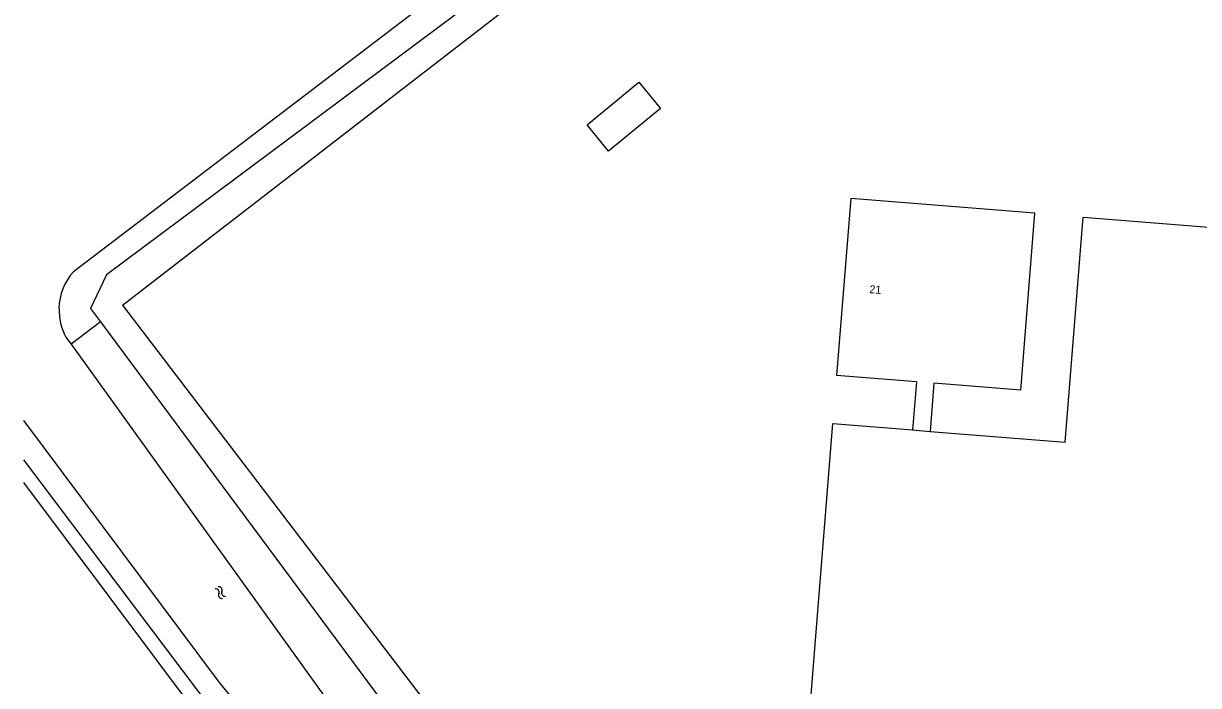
# Model space of a CAD drawing. Extents: x 131000 to 133013, y 393000 to 396501.
# Drawn here: x 131000 to 131146.8, y 394452.9 to 394535.6 of the extents above; entities that cross this region are included whole.
import ezdxf

# ---------------------------------------------------------------- set-up
doc = ezdxf.new("R2010")
doc.units = 0
for name, color, linetype in [('gg-afsc-hekwerk', 7, 'Continuous'), ('gg-anno-huisnummerreeks BGT', 7, 'Continuous'), ('gg-bbg-bijgebouw', 7, 'Continuous'), ('gg-bbg-gedigitaliseerde bebouwing', 7, 'Continuous'), ('gg-bbg-gedigitaliseerde bijgebouw', 7, 'Continuous'), ('gg-bbg-hoofdgebouw', 7, 'Continuous'), ('gg-bbg-tussenscheiding', 7, 'Continuous'), ('gg-kntw-bovenkant insteek waterloop', 7, 'Continuous'), ('gg-kntw-waterlijn', 7, 'Continuous'), ('gt-grn-groengrens', 7, 'Continuous'), ('gt-symb-watersymbool', 7, 'Continuous')]:
    doc.layers.add(name, color=color, linetype=linetype)

# ---------------------------------------------------------------- blocks, each defined once
blk = doc.blocks.new('gt0-WA')
at = {"layer": 'gt-symb-watersymbool'}
for centre, start, end in [((-0.32, 0.02), 28.0725, 151.9275), ((0.43, 0.42), 208.0725, 331.9275), ((-0.32, -0.43), 28.0725, 151.9275), ((0.43, -0.03), 208.0725, 331.9275)]:
    blk.add_arc(centre, 0.425, start, end, dxfattribs=at)

msp = doc.modelspace()

# ---------------------------------------------------------------- linework, layer by layer
at = {"layer": 'gg-afsc-hekwerk'}
for p, q in [((131012.35, 394500.41), (131059.53, 394438.61)), ((131000, 394478.25), (131040.62, 394424))]:
    msp.add_line(p, q, dxfattribs=at)
msp.add_lwpolyline([(131012.35, 394500.41), (131062.93, 394539.51), (131090.58, 394539.97), (131100.72, 394540.82)], dxfattribs=at)
at = {"layer": 'gg-bbg-bijgebouw'}
for points in [[(131130.13, 394483.29), (131132.37, 394511.42), (131203.44, 394505.74), (131196.29, 394415.81)], [(131116.16, 394422), (131096.16, 394423.6), (131101.1, 394485.6)]]:
    msp.add_lwpolyline(points, dxfattribs=at)
at = {"layer": 'gg-bbg-gedigitaliseerde bebouwing'}
for p, q in [((131111.55, 394490.82), (131101.58, 394491.61)), ((131111.55, 394490.82), (131111.07, 394484.81)), ((131113.74, 394490.64), (131113.26, 394484.63)), ((131124.6, 394489.78), (131113.74, 394490.64))]:
    msp.add_line(p, q, dxfattribs=at)
at = {"layer": 'gg-bbg-gedigitaliseerde bijgebouw'}
for p, q in [((131101.1, 394485.6), (131111.07, 394484.81)), ((131113.26, 394484.63), (131130.13, 394483.29))]:
    msp.add_line(p, q, dxfattribs=at)
msp.add_lwpolyline([(131070.4, 394522.94), (131076.88, 394528.28), (131079.58, 394525), (131073.1, 394519.66), (131070.4, 394522.94)], dxfattribs=at)
at = {"layer": 'gg-bbg-hoofdgebouw'}
msp.add_lwpolyline([(131124.6, 394489.78), (131126.36, 394511.9), (131103.34, 394513.73), (131101.58, 394491.61)], dxfattribs=at)
at = {"layer": 'gg-bbg-tussenscheiding'}
msp.add_line((131111.07, 394484.81), (131113.26, 394484.63), dxfattribs=at)
at = {"layer": 'gg-kntw-bovenkant insteek waterloop'}
for p, q in [((131009.62, 394498.32), (131048.49, 394445.93)), ((131000, 394481.07), (131033.4, 394436.78))]:
    msp.add_line(p, q, dxfattribs=at)
msp.add_lwpolyline([(131061.69, 394542.16), (131058.31, 394539.99), (131010.38, 394504.2), (131008.37, 394500), (131009.62, 394498.32)], dxfattribs=at)
at = {"layer": 'gg-kntw-waterlijn'}
msp.add_line((131005.29, 394496.42), (131005.94, 394495.52), dxfattribs=at)
for points in [[(131097.09, 394550.35), (131088.49, 394548.1), (131064.28, 394546.84), (131053.3, 394540.48), (131006.25, 394504.59)], [(131005.94, 394495.52), (131044.57, 394441.82), (131046.47, 394435.82)], [(131000, 394485.98), (131024.45, 394453.25), (131038.77, 394435.72), (131042.82, 394435.39), (131043.89, 394433.98)]]:
    msp.add_lwpolyline(points, dxfattribs=at)
for centre, start, end in [((131011.62, 394499.82), 138.4539, 178.5819), ((131011.63, 394499.82), 178.5731, 208.1989)]:
    msp.add_arc(centre, 7.19, start, end, dxfattribs=at)
at = {"layer": 'gt-grn-groengrens'}
msp.add_line((131009.62, 394498.32), (131005.94, 394495.52), dxfattribs=at)

# ---------------------------------------------------------------- block references
at = {"layer": 'gt-symb-watersymbool', "rotation": -52.6374693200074}
msp.add_blockref('gt0-WA', (131024.56, 394464.53), dxfattribs=at)

# ---------------------------------------------------------------- texts
at = {"layer": 'gg-anno-huisnummerreeks BGT'}
msp.add_text('21', height=1, rotation=355.5, dxfattribs=at).set_placement((131105.64, 394501.92))

doc.saveas('drawing.dxf')
